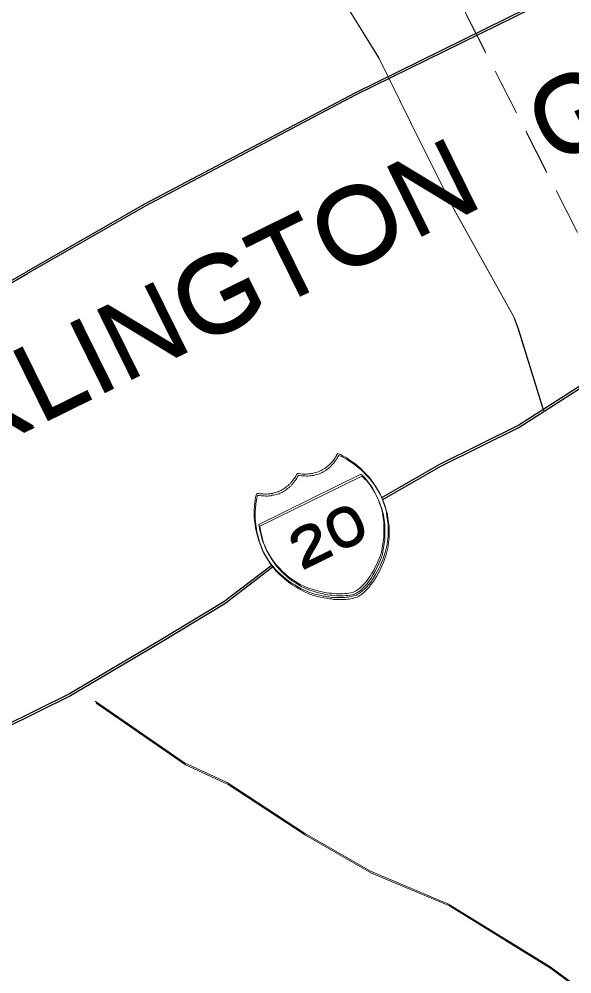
# Model space of a CAD drawing. Extents: x 2356606 to 2371222, y 6973096 to 6982644.
# Drawn here: x 2357363.6 to 2357437.7, y 6973619.6 to 6973747.7 of the extents above; entities that cross this region are included whole.
import ezdxf

# ---------------------------------------------------------------- set-up
doc = ezdxf.new("R2010")
doc.units = 0
doc.header["$LTSCALE"] = 2
doc.linetypes.add('MEDIUM_DASHED', pattern=[4.5, 3, -1.5])
doc.layers.add('62', color=7, linetype='Continuous', lineweight=13)
doc.layers.add('63', color=7, linetype='Continuous', lineweight=13)

msp = doc.modelspace()

# ---------------------------------------------------------------- linework, layer by layer
at = {"layer": '62', "linetype": 'MEDIUM_DASHED'}
msp.add_line((2357358.049, 6973876.711), (2357485.75, 6973626.399), dxfattribs=at)
at = {"layer": '62'}
for p, q in [((2357411.935, 6973742.308), (2357405.378, 6973752.897)), ((2357430.05, 6973707.538), (2357430.606, 6973705.955)), ((2357430.606, 6973705.955), (2357434.03, 6973694.996))]:
    msp.add_line(p, q, dxfattribs=at)
at = {"layer": '62', "lineweight": 25}
msp.add_line((2357344.853, 6973702.151), (2357364.72, 6973713.512), dxfattribs=at)
for points in [[(2357505.855, 6973794.281), (2357494.638, 6973787.314), (2357477.945, 6973775.941), (2357457.618, 6973762.773), (2357434.819, 6973750.341), (2357408.769, 6973737.485), (2357380.527, 6973722.566), (2357364.72, 6973713.512)], [(2357537.893, 6973729.369), (2357522.87, 6973730.109), (2357506.064, 6973725.93), (2357488.655, 6973722.457), (2357466.842, 6973712.87), (2357453.859, 6973707.442), (2357445.268, 6973702.223), (2357430.768, 6973692.911), (2357420.094, 6973687.642), (2357412.343, 6973683.163)], [(2357397.532, 6973674.071), (2357391.187, 6973669.235), (2357382.618, 6973664.025), (2357370.494, 6973656.862), (2357361.535, 6973652.442), (2357355.506, 6973648.488), (2357352.272, 6973643.756), (2357344.159, 6973637.568), (2357331.099, 6973632.303), (2357319.179, 6973627.424), (2357306.189, 6973621.966), (2357287.579, 6973609.643), (2357267.547, 6973602.895), (2357250.669, 6973598.906), (2357239.274, 6973599.379), (2357230.661, 6973609.861), (2357224.807, 6973621.723), (2357220.224, 6973626.738), (2357220.552, 6973637.313)]]:
    msp.add_lwpolyline(points, dxfattribs=at)
at = {"layer": '62'}
for points in [[(2357411.935, 6973742.308), (2357416.235, 6973733.591), (2357421.884, 6973722.15), (2357430.05, 6973707.538)], [(2357401.904, 6973686.367), (2357402.135, 6973686.355), (2357402.338, 6973686.354), (2357402.527, 6973686.372), (2357402.75, 6973686.383), (2357402.943, 6973686.452), (2357403.123, 6973686.441), (2357403.316, 6973686.509), (2357403.495, 6973686.549), (2357403.696, 6973686.599), (2357403.869, 6973686.66), (2357404.05, 6973686.749), (2357404.231, 6973686.838), (2357404.392, 6973686.918), (2357404.554, 6973686.998), (2357404.725, 6973687.107), (2357404.869, 6973687.228), (2357405.011, 6973687.346), (2357405.182, 6973687.456), (2357405.304, 6973687.616), (2357405.455, 6973687.717), (2357405.596, 6973687.888), (2357405.747, 6973688.037), (2357405.87, 6973688.198), (2357405.981, 6973688.378), (2357406.102, 6973688.538), (2357406.213, 6973688.72), (2357406.356, 6973688.942), (2357406.466, 6973689.12), (2357406.82, 6973688.967), (2357407.211, 6973688.785), (2357407.591, 6973688.572), (2357407.973, 6973688.308), (2357408.353, 6973688.044), (2357408.765, 6973687.769), (2357409.135, 6973687.477), (2357409.528, 6973687.142), (2357409.888, 6973686.769), (2357410.247, 6973686.395), (2357410.617, 6973686), (2357410.948, 6973685.584), (2357411.259, 6973685.161), (2357411.536, 6973684.745), (2357411.807, 6973684.304), (2357412.056, 6973683.85), (2357412.283, 6973683.334), (2357412.494, 6973682.809), (2357412.682, 6973682.278), (2357412.849, 6973681.782), (2357412.987, 6973681.248), (2357413.066, 6973680.683), (2357413.152, 6973680.15), (2357413.242, 6973679.616), (2357413.248, 6973679.093), (2357413.226, 6973678.532), (2357413.211, 6973677.997), (2357413.149, 6973677.463), (2357413.077, 6973676.901), (2357412.962, 6973676.368), (2357412.819, 6973675.846), (2357412.644, 6973675.282), (2357412.493, 6973674.88), (2357412.338, 6973674.48), (2357412.166, 6973674.068), (2357411.983, 6973673.676), (2357411.749, 6973673.286), (2357411.524, 6973672.874), (2357411.302, 6973672.512), (2357411.068, 6973672.172), (2357410.836, 6973671.832), (2357410.592, 6973671.51), (2357410.339, 6973671.209), (2357410.044, 6973670.939), (2357409.823, 6973670.727), (2357409.549, 6973670.519), (2357409.317, 6973670.328), (2357409.073, 6973670.208)], [(2357409.073, 6973670.208), (2357408.914, 6973670.129), (2357408.772, 6973670.059), (2357408.572, 6973670.012), (2357408.419, 6973669.961), (2357408.259, 6973669.932), (2357408.047, 6973669.901), (2357407.845, 6973669.854), (2357407.634, 6973669.825), (2357407.413, 6973669.816), (2357407.191, 6973669.806), (2357406.95, 6973669.787), (2357406.749, 6973669.789), (2357406.496, 6973669.79), (2357406.263, 6973669.8), (2357406.034, 6973669.812), (2357405.782, 6973669.813), (2357405.531, 6973669.865), (2357405.268, 6973669.887), (2357405.008, 6973669.908), (2357404.776, 6973669.967), (2357404.535, 6973670), (2357404.276, 6973670.073), (2357404.014, 6973670.093), (2357403.801, 6973670.166), (2357403.551, 6973670.218), (2357403.318, 6973670.278), (2357403.059, 6973670.351), (2357402.84, 6973670.442), (2357402.597, 6973670.523), (2357402.385, 6973670.596), (2357402.196, 6973670.679), (2357401.962, 6973670.789), (2357401.542, 6973670.983), (2357401.122, 6973671.226), (2357400.692, 6973671.49), (2357400.318, 6973671.734), (2357399.906, 6973672.007), (2357399.506, 6973672.311), (2357399.135, 6973672.603), (2357398.774, 6973672.929), (2357398.434, 6973673.26), (2357398.084, 6973673.616), (2357397.773, 6973673.989), (2357397.463, 6973674.365), (2357397.164, 6973674.767), (2357396.905, 6973675.191), (2357396.623, 6973675.654), (2357396.375, 6973676.111), (2357396.186, 6973676.594), (2357395.998, 6973677.079), (2357395.821, 6973677.542), (2357395.692, 6973678.056), (2357395.565, 6973678.571), (2357395.455, 6973679.092), (2357395.377, 6973679.607), (2357395.3, 6973680.12), (2357395.271, 6973680.634), (2357395.264, 6973681.106), (2357395.277, 6973681.591), (2357395.32, 6973682.064), (2357395.361, 6973682.536), (2357395.407, 6973682.959), (2357395.5, 6973683.38), (2357395.593, 6973683.753), (2357395.823, 6973683.742), (2357396.066, 6973683.712), (2357396.295, 6973683.698), (2357396.478, 6973683.689), (2357396.708, 6973683.675), (2357396.909, 6973683.674), (2357397.12, 6973683.704), (2357397.342, 6973683.714), (2357397.514, 6973683.772), (2357397.715, 6973683.772), (2357397.908, 6973683.843), (2357398.087, 6973683.881), (2357398.287, 6973683.929), (2357398.46, 6973683.99), (2357398.623, 6973684.071), (2357398.825, 6973684.168), (2357398.964, 6973684.239), (2357399.147, 6973684.327), (2357399.299, 6973684.427), (2357399.459, 6973684.558), (2357399.604, 6973684.677), (2357399.754, 6973684.778), (2357399.896, 6973684.948), (2357400.065, 6973685.058), (2357400.167, 6973685.208), (2357400.321, 6973685.358), (2357400.462, 6973685.528), (2357400.594, 6973685.72), (2357400.694, 6973685.87), (2357400.826, 6973686.059), (2357400.928, 6973686.26), (2357401.061, 6973686.452), (2357401.27, 6973686.43), (2357401.47, 6973686.377), (2357401.704, 6973686.368), (2357401.904, 6973686.367)], [(2357533.197, 6973606.326), (2357524.62, 6973605.458), (2357515.167, 6973602.848), (2357498.075, 6973598.379), (2357486.108, 6973599.448), (2357477.959, 6973600.342), (2357467.348, 6973601.705), (2357455.307, 6973606.229), (2357445.287, 6973612.652), (2357434.9, 6973620.272), (2357421.318, 6973628.676), (2357410.865, 6973633.077), (2357401.996, 6973638.183), (2357391.636, 6973644.988), (2357385.904, 6973647.606), (2357373.931, 6973655.899)]]:
    msp.add_lwpolyline(points, dxfattribs=at)
msp.add_lwpolyline([(2357409.563, 6973686.356), (2357395.901, 6973679.616), (2357395.941, 6973679.382), (2357395.958, 6973679.091), (2357396.016, 6973678.769), (2357396.146, 6973678.356), (2357396.235, 6973677.923), (2357396.383, 6973677.419), (2357396.591, 6973676.894), (2357396.84, 6973676.339), (2357397.139, 6973675.784), (2357397.457, 6973675.239), (2357397.816, 6973674.714), (2357398.177, 6973674.24), (2357398.586, 6973673.764), (2357398.997, 6973673.34), (2357399.458, 6973672.915), (2357399.92, 6973672.541), (2357400.392, 6973672.197), (2357400.915, 6973671.851), (2357401.436, 6973671.556), (2357401.998, 6973671.284), (2357402.59, 6973671.047), (2357403.161, 6973670.854), (2357403.775, 6973670.68), (2357404.388, 6973670.554), (2357404.69, 6973670.453), (2357405, 6973670.43), (2357405.302, 6973670.38), (2357405.635, 6973670.369), (2357405.907, 6973670.325), (2357406.227, 6973670.284), (2357406.531, 6973670.284), (2357406.851, 6973670.291), (2357407.123, 6973670.3), (2357407.415, 6973670.319), (2357407.709, 6973670.338), (2357407.94, 6973670.376), (2357408.19, 6973670.425), (2357408.413, 6973670.483), (2357408.655, 6973670.554), (2357408.856, 6973670.652), (2357409.129, 6973670.813), (2357409.442, 6973671.043), (2357409.685, 6973671.313), (2357410.007, 6973671.623), (2357410.294, 6973671.914), (2357410.537, 6973672.286), (2357410.8, 6973672.666), (2357411.055, 6973673.066), (2357411.297, 6973673.489), (2357411.502, 6973673.891), (2357411.703, 6973674.292), (2357411.897, 6973674.712), (2357412.081, 6973675.104), (2357412.193, 6973675.487), (2357412.318, 6973675.848), (2357412.377, 6973676.18), (2357412.481, 6973676.733), (2357412.554, 6973677.296), (2357412.628, 6973677.809), (2357412.651, 6973678.373), (2357412.663, 6973678.856), (2357412.655, 6973679.328), (2357412.649, 6973679.801), (2357412.59, 6973680.274), (2357412.531, 6973680.749), (2357412.474, 6973681.172), (2357412.356, 6973681.615), (2357412.227, 6973682.026), (2357412.079, 6973682.429), (2357411.95, 6973682.844), (2357411.761, 6973683.226), (2357411.592, 6973683.62), (2357411.303, 6973684.155), (2357411.014, 6973684.64), (2357410.723, 6973685.073), (2357410.474, 6973685.428), (2357410.183, 6973685.759), (2357409.943, 6973685.993), (2357409.743, 6973686.194)], close=True, dxfattribs=at)
at = {"layer": '63', "linetype": 'MEDIUM_DASHED'}
msp.add_line((2357357.919, 6973876.974), (2357485.62, 6973626.662), dxfattribs=at)
at = {"layer": '63'}
for p, q in [((2357411.805, 6973742.571), (2357405.248, 6973753.16)), ((2357429.92, 6973707.801), (2357430.476, 6973706.218)), ((2357430.476, 6973706.218), (2357433.9, 6973695.259))]:
    msp.add_line(p, q, dxfattribs=at)
at = {"layer": '63', "lineweight": 25}
msp.add_line((2357344.723, 6973702.414), (2357364.59, 6973713.775), dxfattribs=at)
for points in [[(2357505.725, 6973794.544), (2357494.508, 6973787.577), (2357477.815, 6973776.204), (2357457.488, 6973763.036), (2357434.689, 6973750.604), (2357408.639, 6973737.748), (2357380.397, 6973722.829), (2357364.59, 6973713.775)], [(2357537.763, 6973729.632), (2357522.74, 6973730.372), (2357505.934, 6973726.193), (2357488.525, 6973722.72), (2357466.712, 6973713.133), (2357453.729, 6973707.705), (2357445.138, 6973702.486), (2357430.638, 6973693.174), (2357419.964, 6973687.905), (2357412.213, 6973683.426)], [(2357397.402, 6973674.334), (2357391.057, 6973669.498), (2357382.488, 6973664.288), (2357370.364, 6973657.125), (2357361.405, 6973652.705), (2357355.376, 6973648.751), (2357352.142, 6973644.019), (2357344.029, 6973637.831), (2357330.969, 6973632.566), (2357319.049, 6973627.687), (2357306.059, 6973622.229), (2357287.449, 6973609.906), (2357267.417, 6973603.158), (2357250.539, 6973599.169), (2357239.144, 6973599.642), (2357230.531, 6973610.124), (2357224.677, 6973621.986), (2357220.094, 6973627.001), (2357220.422, 6973637.576)]]:
    msp.add_lwpolyline(points, dxfattribs=at)
at = {"layer": '63'}
for points in [[(2357411.805, 6973742.571), (2357416.105, 6973733.854), (2357421.754, 6973722.413), (2357429.92, 6973707.801)], [(2357401.774, 6973686.63), (2357402.005, 6973686.618), (2357402.208, 6973686.617), (2357402.397, 6973686.635), (2357402.62, 6973686.646), (2357402.813, 6973686.715), (2357402.993, 6973686.704), (2357403.186, 6973686.772), (2357403.365, 6973686.812), (2357403.566, 6973686.862), (2357403.739, 6973686.923), (2357403.92, 6973687.012), (2357404.101, 6973687.101), (2357404.262, 6973687.181), (2357404.424, 6973687.261), (2357404.595, 6973687.37), (2357404.739, 6973687.491), (2357404.881, 6973687.609), (2357405.052, 6973687.719), (2357405.174, 6973687.879), (2357405.325, 6973687.98), (2357405.466, 6973688.151), (2357405.617, 6973688.3), (2357405.74, 6973688.461), (2357405.851, 6973688.641), (2357405.972, 6973688.801), (2357406.083, 6973688.983), (2357406.226, 6973689.205), (2357406.336, 6973689.383), (2357406.69, 6973689.23), (2357407.081, 6973689.048), (2357407.461, 6973688.835), (2357407.843, 6973688.571), (2357408.223, 6973688.307), (2357408.635, 6973688.032), (2357409.005, 6973687.74), (2357409.398, 6973687.405), (2357409.758, 6973687.032), (2357410.117, 6973686.658), (2357410.487, 6973686.263), (2357410.818, 6973685.847), (2357411.129, 6973685.424), (2357411.406, 6973685.008), (2357411.677, 6973684.567), (2357411.926, 6973684.113), (2357412.153, 6973683.597), (2357412.364, 6973683.072), (2357412.552, 6973682.541), (2357412.719, 6973682.045), (2357412.857, 6973681.511), (2357412.936, 6973680.946), (2357413.022, 6973680.413), (2357413.112, 6973679.879), (2357413.118, 6973679.356), (2357413.096, 6973678.795), (2357413.081, 6973678.26), (2357413.019, 6973677.726), (2357412.947, 6973677.164), (2357412.832, 6973676.631), (2357412.689, 6973676.109), (2357412.514, 6973675.545), (2357412.363, 6973675.143), (2357412.208, 6973674.743), (2357412.036, 6973674.331), (2357411.853, 6973673.939), (2357411.619, 6973673.549), (2357411.394, 6973673.137), (2357411.172, 6973672.775), (2357410.938, 6973672.435), (2357410.706, 6973672.095), (2357410.462, 6973671.773), (2357410.209, 6973671.472), (2357409.914, 6973671.202), (2357409.693, 6973670.99), (2357409.419, 6973670.782), (2357409.187, 6973670.591), (2357408.943, 6973670.471)], [(2357408.943, 6973670.471), (2357408.784, 6973670.392), (2357408.642, 6973670.322), (2357408.442, 6973670.275), (2357408.289, 6973670.224), (2357408.129, 6973670.195), (2357407.917, 6973670.164), (2357407.715, 6973670.117), (2357407.504, 6973670.088), (2357407.283, 6973670.079), (2357407.061, 6973670.069), (2357406.82, 6973670.05), (2357406.619, 6973670.052), (2357406.366, 6973670.053), (2357406.133, 6973670.063), (2357405.904, 6973670.075), (2357405.652, 6973670.076), (2357405.401, 6973670.128), (2357405.138, 6973670.15), (2357404.878, 6973670.171), (2357404.646, 6973670.23), (2357404.405, 6973670.263), (2357404.146, 6973670.336), (2357403.884, 6973670.356), (2357403.671, 6973670.429), (2357403.421, 6973670.481), (2357403.188, 6973670.541), (2357402.929, 6973670.614), (2357402.71, 6973670.705), (2357402.467, 6973670.786), (2357402.255, 6973670.859), (2357402.066, 6973670.942), (2357401.832, 6973671.052), (2357401.412, 6973671.246), (2357400.992, 6973671.489), (2357400.562, 6973671.753), (2357400.188, 6973671.997), (2357399.776, 6973672.27), (2357399.376, 6973672.574), (2357399.005, 6973672.866), (2357398.644, 6973673.192), (2357398.304, 6973673.523), (2357397.954, 6973673.879), (2357397.643, 6973674.252), (2357397.333, 6973674.628), (2357397.034, 6973675.03), (2357396.775, 6973675.454), (2357396.493, 6973675.917), (2357396.245, 6973676.374), (2357396.056, 6973676.857), (2357395.868, 6973677.342), (2357395.691, 6973677.805), (2357395.562, 6973678.319), (2357395.435, 6973678.834), (2357395.325, 6973679.355), (2357395.247, 6973679.87), (2357395.17, 6973680.383), (2357395.141, 6973680.897), (2357395.134, 6973681.369), (2357395.147, 6973681.854), (2357395.19, 6973682.327), (2357395.231, 6973682.799), (2357395.277, 6973683.222), (2357395.37, 6973683.643), (2357395.463, 6973684.016), (2357395.693, 6973684.005), (2357395.936, 6973683.975), (2357396.165, 6973683.961), (2357396.348, 6973683.952), (2357396.578, 6973683.938), (2357396.779, 6973683.937), (2357396.99, 6973683.967), (2357397.212, 6973683.977), (2357397.384, 6973684.035), (2357397.585, 6973684.035), (2357397.778, 6973684.106), (2357397.957, 6973684.144), (2357398.157, 6973684.192), (2357398.33, 6973684.253), (2357398.493, 6973684.334), (2357398.695, 6973684.431), (2357398.834, 6973684.502), (2357399.017, 6973684.59), (2357399.169, 6973684.69), (2357399.329, 6973684.821), (2357399.474, 6973684.94), (2357399.624, 6973685.041), (2357399.766, 6973685.211), (2357399.935, 6973685.321), (2357400.037, 6973685.471), (2357400.191, 6973685.621), (2357400.332, 6973685.791), (2357400.464, 6973685.983), (2357400.564, 6973686.133), (2357400.696, 6973686.322), (2357400.798, 6973686.523), (2357400.931, 6973686.715), (2357401.14, 6973686.693), (2357401.34, 6973686.64), (2357401.574, 6973686.631), (2357401.774, 6973686.63)], [(2357533.067, 6973606.589), (2357524.49, 6973605.721), (2357515.037, 6973603.111), (2357497.945, 6973598.642), (2357485.978, 6973599.711), (2357477.829, 6973600.605), (2357467.218, 6973601.968), (2357455.177, 6973606.492), (2357445.157, 6973612.915), (2357434.77, 6973620.535), (2357421.188, 6973628.939), (2357410.735, 6973633.34), (2357401.866, 6973638.446), (2357391.506, 6973645.251), (2357385.774, 6973647.869), (2357373.801, 6973656.162)]]:
    msp.add_lwpolyline(points, dxfattribs=at)
msp.add_lwpolyline([(2357409.433, 6973686.619), (2357395.771, 6973679.879), (2357395.811, 6973679.645), (2357395.828, 6973679.354), (2357395.886, 6973679.032), (2357396.016, 6973678.619), (2357396.105, 6973678.186), (2357396.253, 6973677.682), (2357396.461, 6973677.157), (2357396.71, 6973676.602), (2357397.009, 6973676.047), (2357397.327, 6973675.502), (2357397.686, 6973674.977), (2357398.047, 6973674.503), (2357398.456, 6973674.027), (2357398.867, 6973673.603), (2357399.328, 6973673.178), (2357399.79, 6973672.804), (2357400.262, 6973672.46), (2357400.785, 6973672.114), (2357401.306, 6973671.819), (2357401.868, 6973671.547), (2357402.46, 6973671.31), (2357403.031, 6973671.117), (2357403.645, 6973670.943), (2357404.258, 6973670.817), (2357404.56, 6973670.716), (2357404.87, 6973670.693), (2357405.172, 6973670.643), (2357405.505, 6973670.632), (2357405.777, 6973670.588), (2357406.097, 6973670.547), (2357406.401, 6973670.547), (2357406.721, 6973670.554), (2357406.993, 6973670.563), (2357407.285, 6973670.582), (2357407.579, 6973670.601), (2357407.81, 6973670.639), (2357408.06, 6973670.688), (2357408.283, 6973670.746), (2357408.525, 6973670.817), (2357408.726, 6973670.915), (2357408.999, 6973671.076), (2357409.312, 6973671.306), (2357409.555, 6973671.576), (2357409.877, 6973671.886), (2357410.164, 6973672.177), (2357410.407, 6973672.549), (2357410.67, 6973672.929), (2357410.925, 6973673.329), (2357411.167, 6973673.752), (2357411.372, 6973674.154), (2357411.573, 6973674.555), (2357411.767, 6973674.975), (2357411.951, 6973675.367), (2357412.063, 6973675.75), (2357412.188, 6973676.111), (2357412.247, 6973676.443), (2357412.351, 6973676.996), (2357412.424, 6973677.559), (2357412.498, 6973678.072), (2357412.521, 6973678.636), (2357412.533, 6973679.119), (2357412.525, 6973679.591), (2357412.519, 6973680.064), (2357412.46, 6973680.537), (2357412.401, 6973681.012), (2357412.344, 6973681.435), (2357412.226, 6973681.878), (2357412.097, 6973682.289), (2357411.949, 6973682.692), (2357411.82, 6973683.107), (2357411.631, 6973683.489), (2357411.462, 6973683.883), (2357411.173, 6973684.418), (2357410.884, 6973684.903), (2357410.593, 6973685.336), (2357410.344, 6973685.691), (2357410.053, 6973686.022), (2357409.813, 6973686.256), (2357409.613, 6973686.457)], close=True, dxfattribs=at)

# ---------------------------------------------------------------- texts
at = {"layer": '62'}
for s, height, width, p in [('GRAND', 10.21, 1.05, (2357435.168, 6973727.828)), ('ARLINGTON', 10.21, 1.1, (2357347.651, 6973683.932)), ('20', 5.099, 1.4, (2357401.426, 6973673.561))]:
    msp.add_text(s, height=height, rotation=26.268, dxfattribs=dict(at, width=width)).set_placement(p)
at = {"layer": '63'}
for s, height, width, p in [('GRAND', 10.21, 1.05, (2357435.038, 6973728.092)), ('ARLINGTON', 10.21, 1.1, (2357347.521, 6973684.196)), ('20', 5.099, 1.4, (2357401.296, 6973673.825))]:
    msp.add_text(s, height=height, rotation=26.268, dxfattribs=dict(at, width=width)).set_placement(p)

doc.saveas('drawing.dxf')
